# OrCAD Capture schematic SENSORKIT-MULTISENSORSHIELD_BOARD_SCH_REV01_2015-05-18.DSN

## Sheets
1 P01: RevisionHist: title: Sensor Platform Multi-Sensor Shield; rev: 01; note: Table of Contents/Revision History
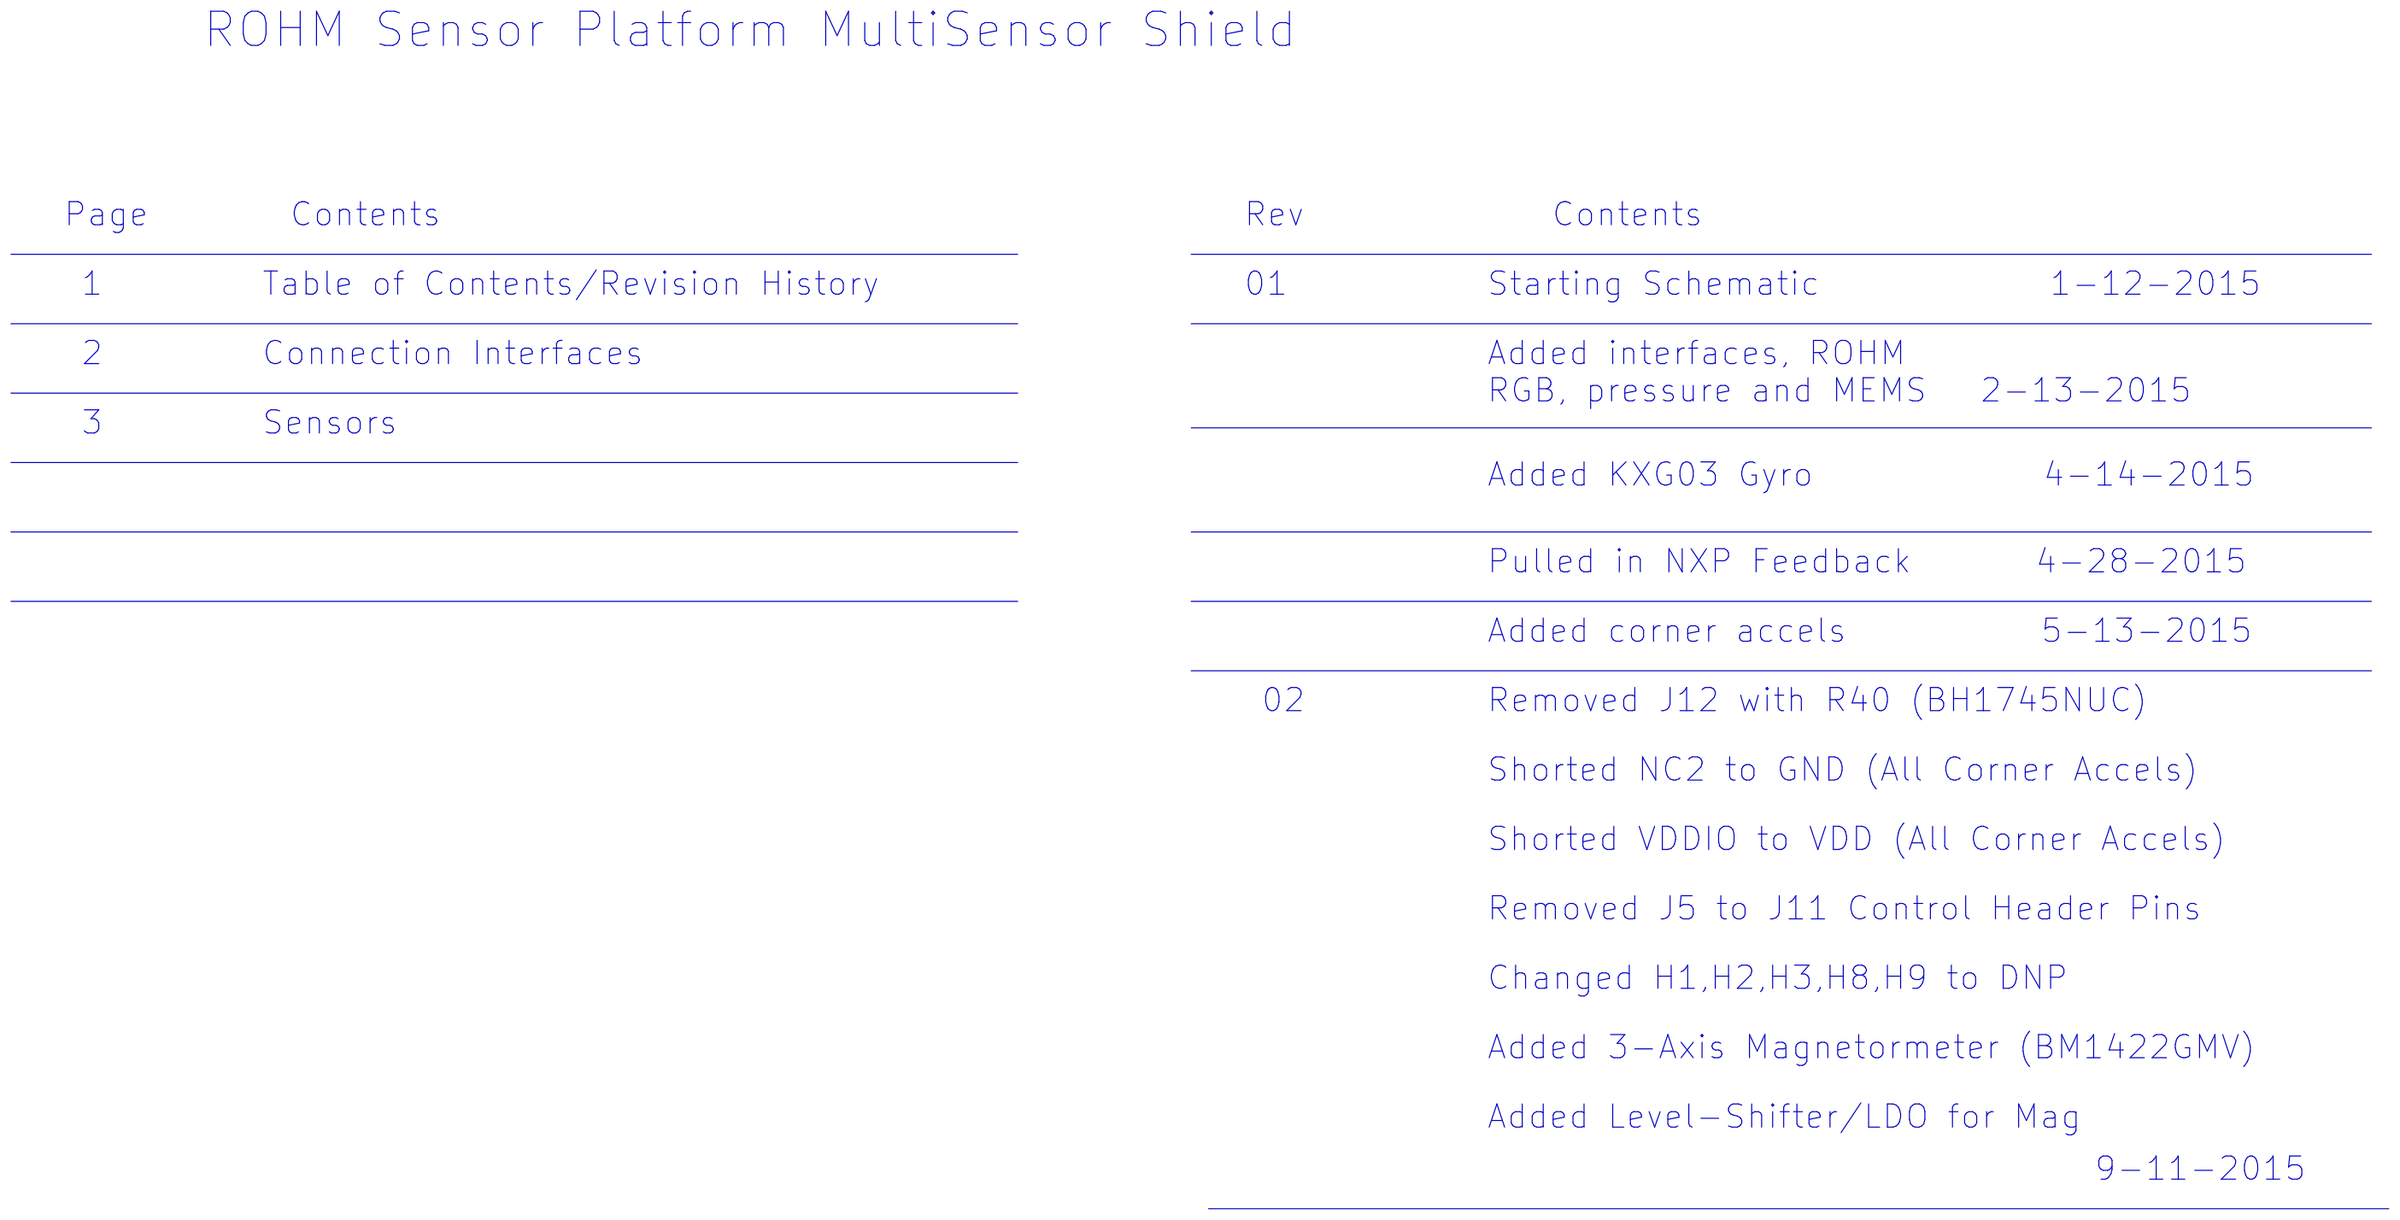
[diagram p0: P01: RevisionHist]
2 P03: Sensors: size C; note: Sensors
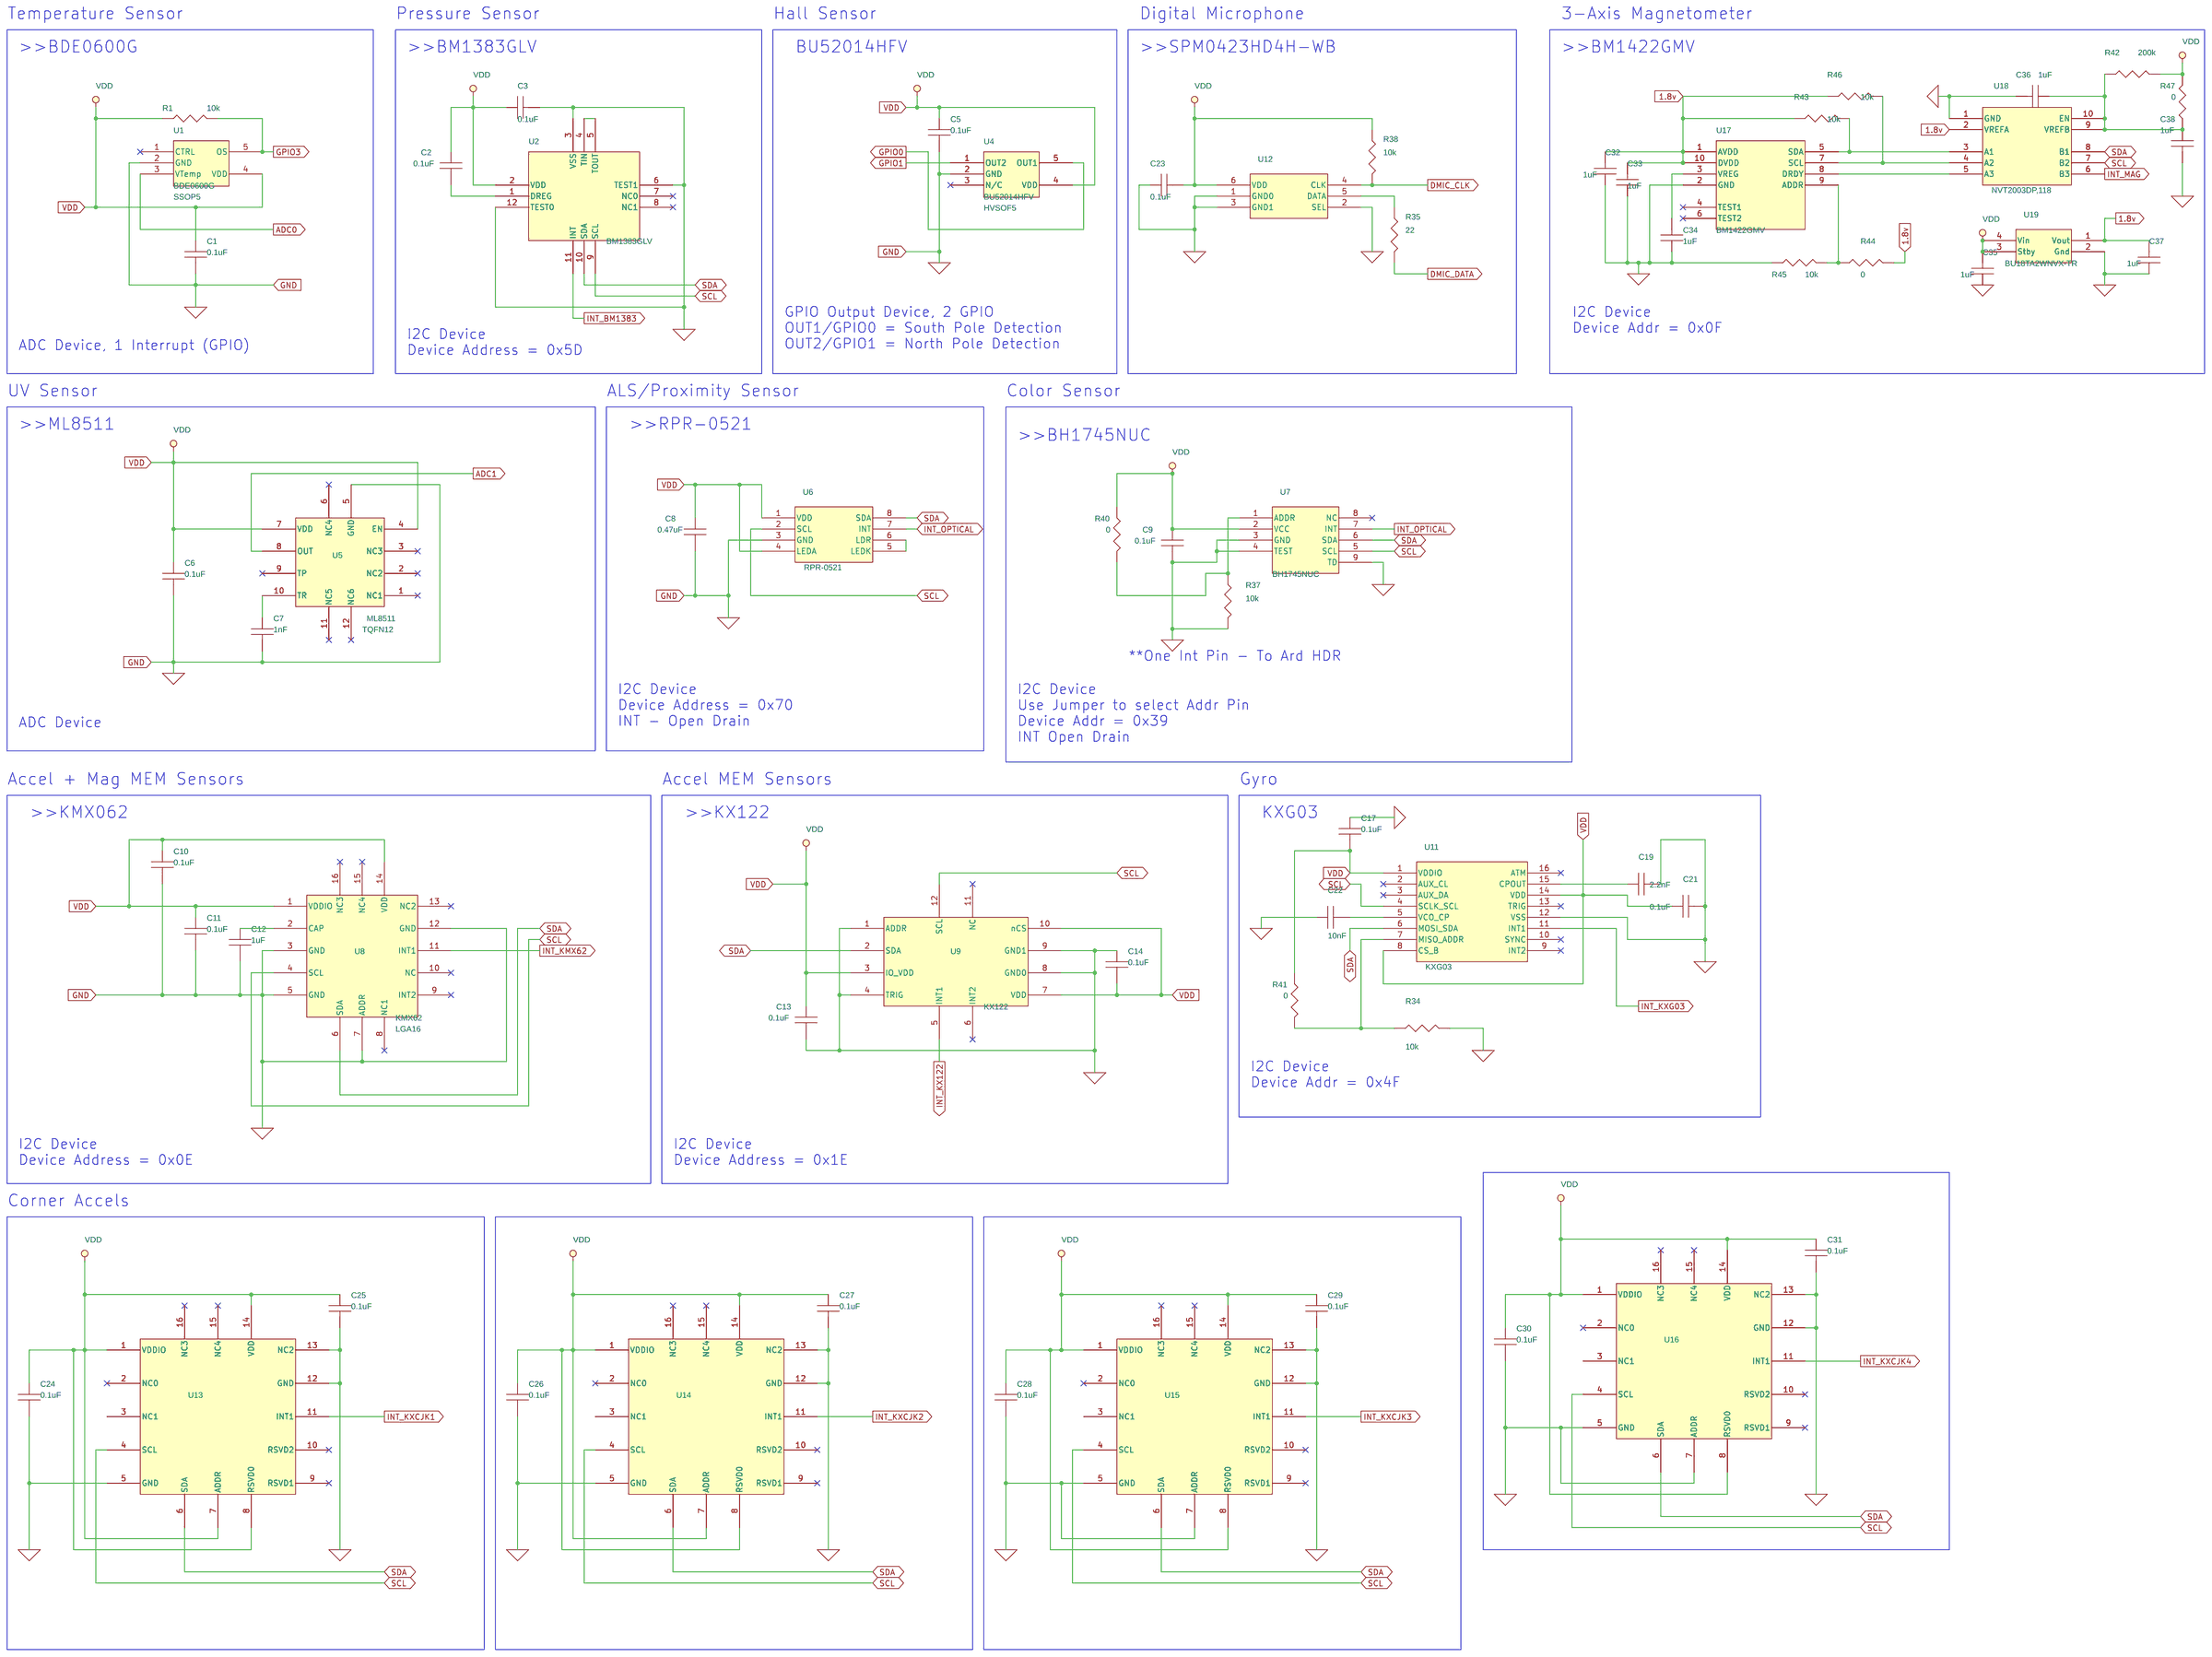
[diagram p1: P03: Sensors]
3 P02: Connection Interface: size B; note: Connection Interface
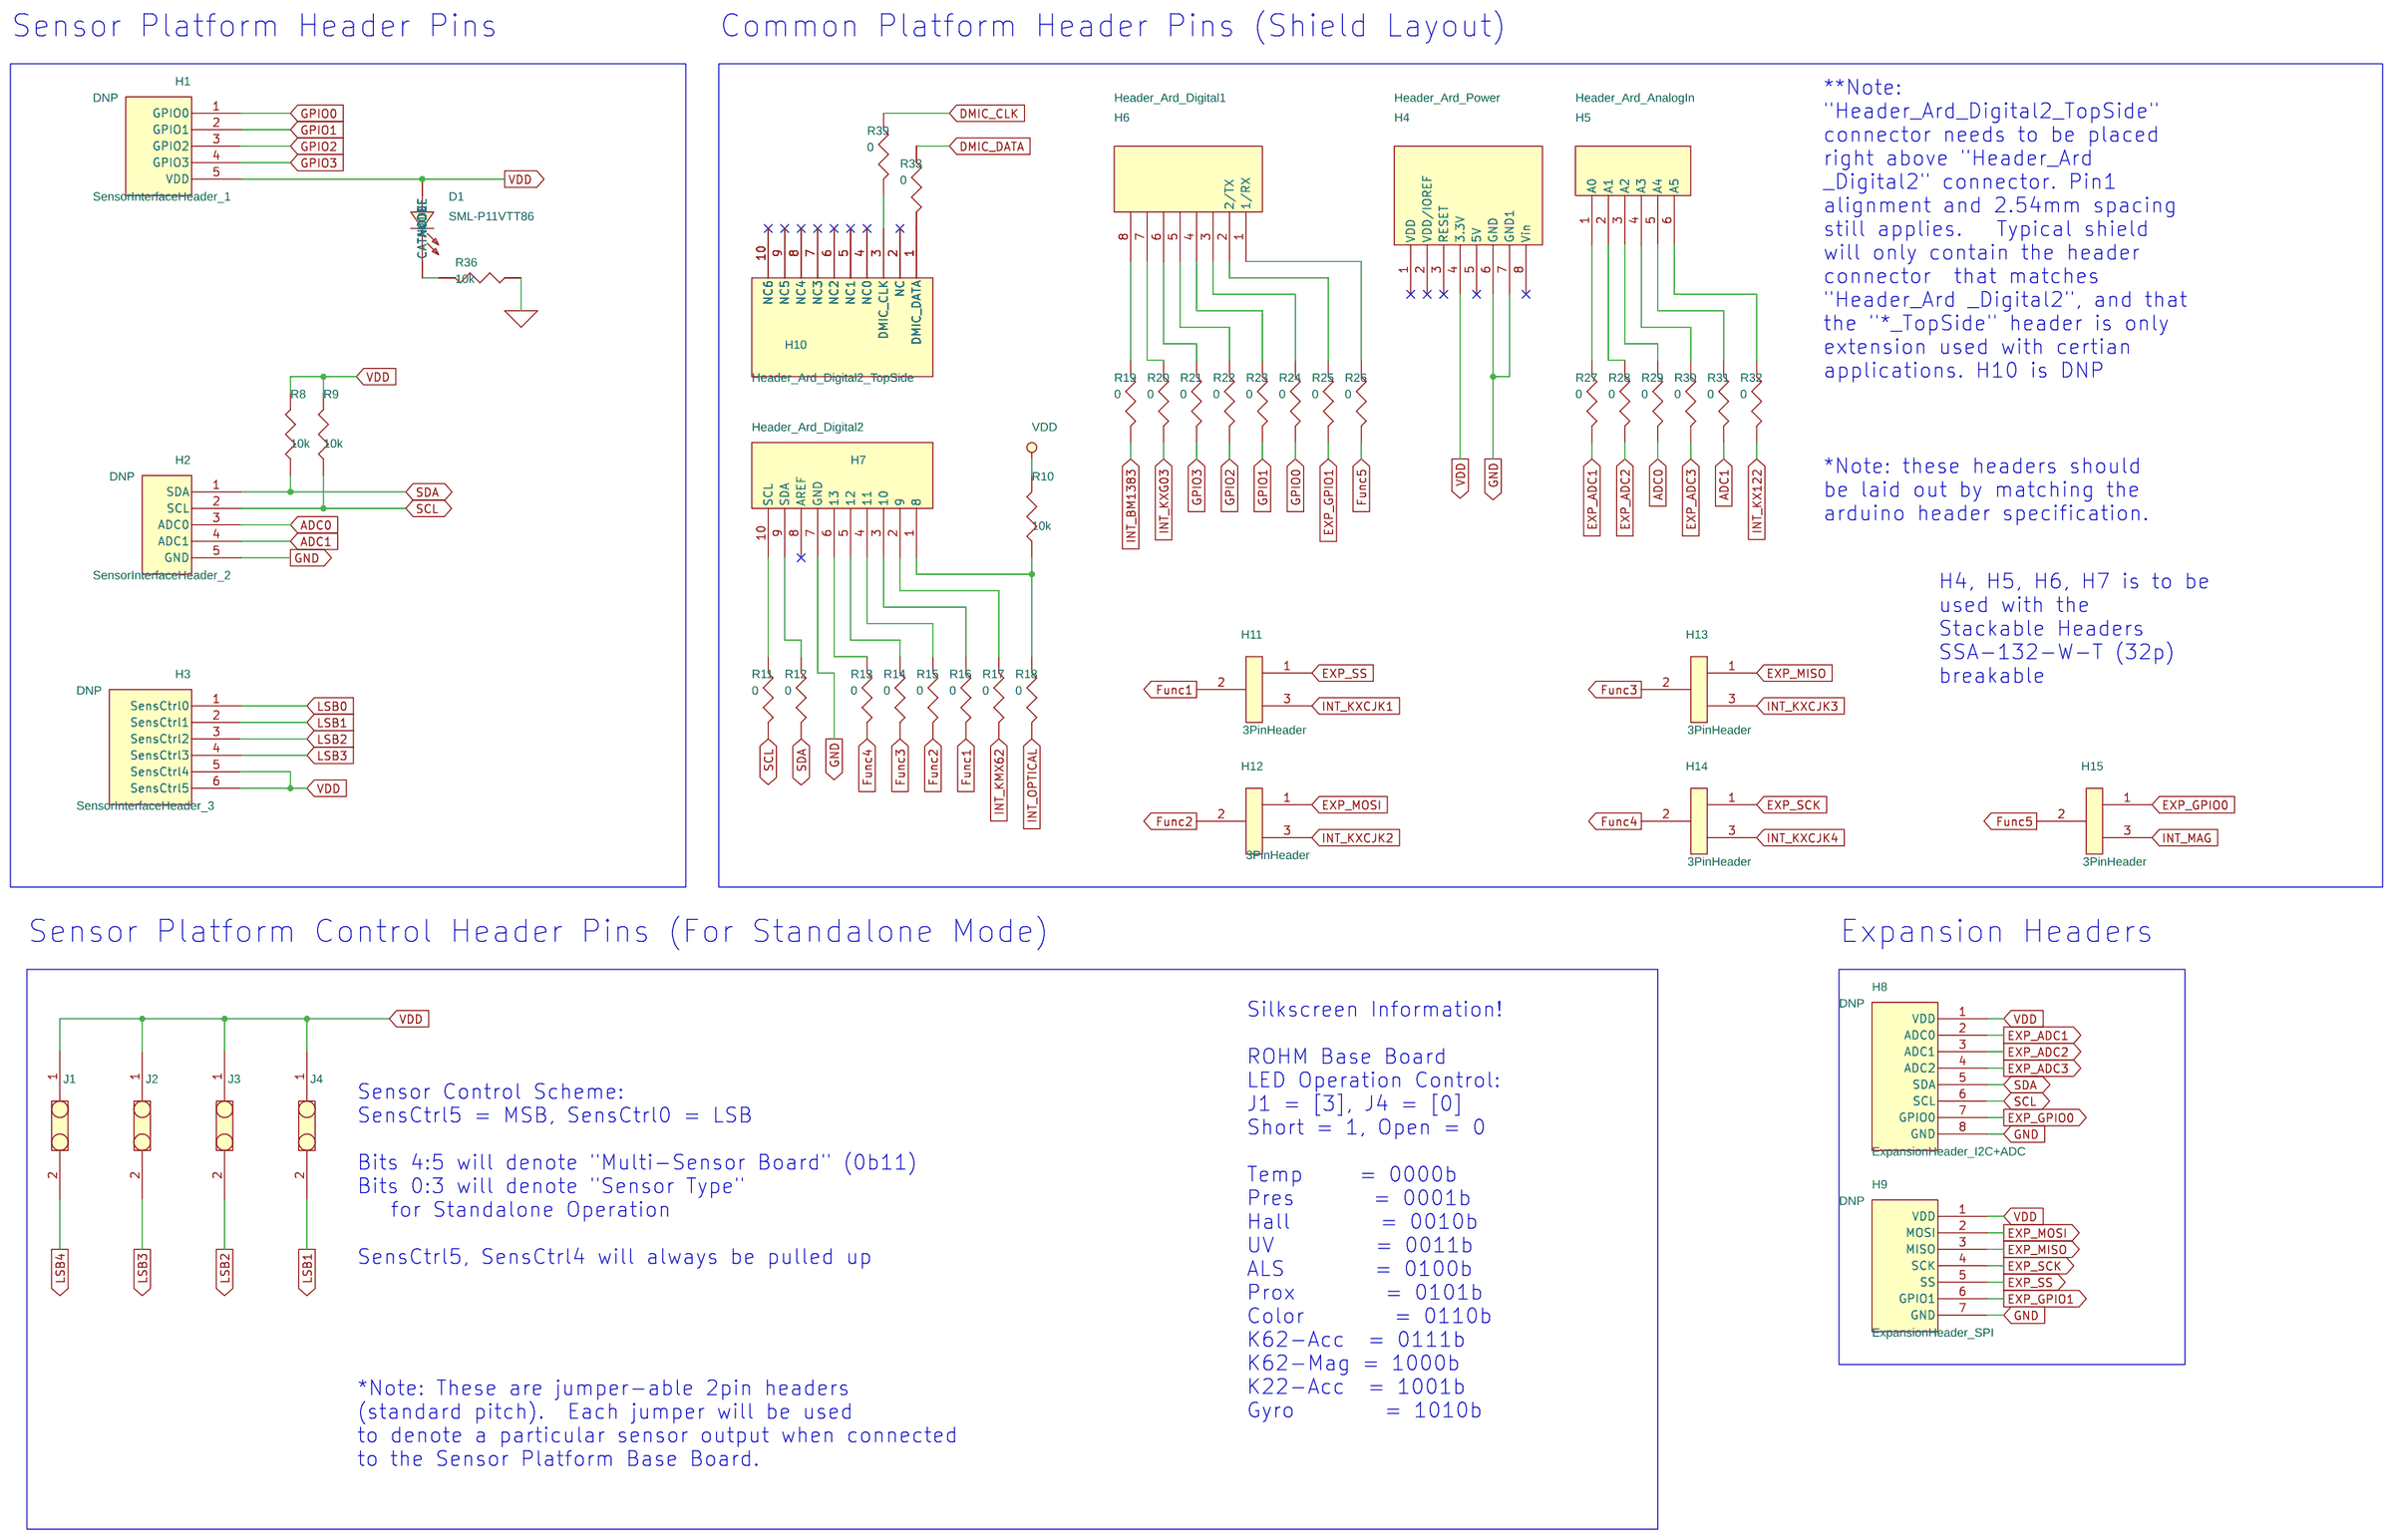
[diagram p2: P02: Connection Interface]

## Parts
sheet P02: Connection Interface
D1  SML-P11VTT86  [LED0402]
H1  SensorInterfaceHeader_1  [HDR_THVT_1X5_100]
H2  SensorInterfaceHeader_2  [HDR_THVT_1X5_100]
H3  SensorInterfaceHeader_3  [HDR_THVT_1X6_100]
H4  Header_Ard_Power  [HDR_THVT_1X8_100]
H5  Header_Ard_AnalogIn  [HDR_THVT_1X6_100]
H6  Header_Ard_Digital1  [HDR_THVT_1X8_100]
H7  Header_Ard_Digital2  [HDR_THVT_1X10_100]
H8  ExpansionHeader_I2C+ADC  [HDR_THVT_1X8_100]
H9  ExpansionHeader_SPI  [HDR_THVT_1X7_100]
H10  Header_Ard_Digital2_TopSide  [HDR_THVT_1X10_100]
H11  3PinHeader  [HDR_THVT_1X3_100]
H12  3PinHeader  [HDR_THVT_1X3_100]
H13  3PinHeader  [HDR_THVT_1X3_100]
H14  3PinHeader  [HDR_THVT_1X3_100]
H15  3PinHeader  [HDR_THVT_1X3_100]
J1  2-Pin Header  [HDR_THVT_1X2_100]
J2  2-Pin Header  [HDR_THVT_1X2_100]
J3  2-Pin Header  [HDR_THVT_1X2_100]
J4  2-Pin Header  [HDR_THVT_1X2_100]
R8  10k  [R0603]
R9  10k  [R0603]
R10  10k  [R0603]
R11  0  [R0603]
R12  0  [R0603]
R13  0  [R0603]
R14  0  [R0603]
R15  0  [R0603]
R16  0  [R0603]
R17  0  [R0603]
R18  0  [R0603]
R19  0  [R0603]
R20  0  [R0603]
R21  0  [R0603]
R22  0  [R0603]
R23  0  [R0603]
R24  0  [R0603]
R25  0  [R0603]
R26  0  [R0603]
R27  0  [R0603]
R28  0  [R0603]
R29  0  [R0603]
R30  0  [R0603]
R31  0  [R0603]
R32  0  [R0603]
R33  0  [R0603]
R36  10k  [R0603]
R39  0  [R0603]
sheet P03: Sensors
C1  0.1uF  [C0402]
C2  0.1uF  [C0402]
C3  0.1uF  [C0402]
C5  0.1uF  [C0402]
C6  0.1uF  [C0402]
C7  1nF  [C0402]
C8  0.47uF  [C0402]
C9  0.1uF  [C0402]
C10  0.1uF  [C0402]
C11  0.1uF  [C0402]
C12  1uF  [C0402]
C13  0.1uF  [C0402]
C14  0.1uF  [C0402]
C17  0.1uF  [C0402]
C19  2.2nF  [C0402]
C21  0.1uF  [C0402]
C22  10nF  [C0402]
C23  0.1uF  [C0402]
C24  0.1uF  [C0402]
C25  0.1uF  [C0402]
C26  0.1uF  [C0402]
C27  0.1uF  [C0402]
C28  0.1uF  [C0402]
C29  0.1uF  [C0402]
C30  0.1uF  [C0402]
C31  0.1uF  [C0402]
C32  1uF  [C0402]
C33  1uF  [C0402]
C34  1uF  [C0402]
C35  1uF  [C0402]
C36  1uF  [C0402]
C37  1uF  [C0402]
C38  1uF  [C0402]
R1  10k  [R0603]
R34  10k  [R0603]
R35  22  [R0603]
R37  10k  [R0603]
R38  10k  [R0603]
R40  0  [R0603]
R41  0  [R0603]
R42  200k  [R0603]
R43  10k  [R0603]
R44  0  [R0603]
R45  10k  [R0603]
R46  10k  [R0603]
R47  0  [R0603]
U1  BDE0600G  [SSOP5]
U2  BM1383GLV  [BM1383GLV]
U4  BU52014HFV  [HVSOF5]
U5  ML8511  [TQFN12]
U6  RPR-0521  [IC_3P94X2P36]
U7  BH1745NUC  [BH1745NUC]
U8  KMX62  [LGA_3x3x0P9]
U9  KX122  [LGA_2x2x0P9]
U11  KXG03  [LGA_3x3x0P9]
U12  SPM0423HD4H-WB  [IC_4P72X3P76]
U13  EVAL-KXCJK-1013  [LGA_3X3X0P9]
U14  EVAL-KXCJK-1013  [LGA_3X3X0P9]
U15  EVAL-KXCJK-1013  [LGA_3X3X0P9]
U16  EVAL-KXCJK-1013  [LGA_3X3X0P9]
U17  BM1422GMV  [MLLGA010V020A]
U18  NVT2003DP,118  [TSSOP10]
U19  BU18TA2WNVX-TR  [4SSON-EP]

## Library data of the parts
D1 = LED_0: LED 0402 RED 50MW 20MA SMD; DISTR1: ROHM; MFG1: ROHM; PACKAGE: 0403
H1 = SensorInterfaceHeader_1: CONN HEADER VERT SGL 5POS GOLD; DNP: DNP; Distr1: DIGIKEY; Distr1_part#: 3M9450-ND; Mfg1: 3M; Mfg1_part#: 961105-6404-AR
H2 = SensorInterfaceHeader_2: CONN HEADER VERT SGL 5POS GOLD; DNP: DNP; Distr1: DIGIKEY; Distr1_part#: 3M9450-ND; Mfg1: 3M; Mfg1_part#: 961105-6404-AR
H3 = SensorInterfaceHeader_3: CONN HEADER VERT SGL 6POS GOLD; DNP: DNP; Distr1: DIGIKEY; Distr1_part#: 3M9451-ND; Mfg1: 3M; Mfg1_part#: 961106-6404-AR
H4 = Header_Ard_Power_0
H5 = Header_Ard_AnalogIn
H6 = Header_Ard_Digital1_0
H7 = Header_Ard_Digital2
H8 = ExpansionHeader_I2C+ADC_0: DNP: DNP
H9 = ExpansionHeader_SPI_0: DNP: DNP
H10 = Header_Ard_Digital2_TopSide
H11-H15 = 3PinHeader
J1-J4 = 2-Pin_Header
R8-R10 = R: RES SMD 10K OHM 5% 1/10W 0603; BOM: EMPTY; Distr1: DIGIKEY; Distr1_part#: RHM10KCGTR-ND; Mfg1: Rohm Semiconductor; Mfg1_part#: MCR03ERTJ103; Package: 0603; Part Number: MCR03ERTJ103; Power: 0.1W, 1/10W; Tolerance: ±5%
R11-R33 R40 R41 R44 = R: RES 0.0 OHM 1/10W JUMP 0603 SMD; DISTR1: DIGIKEY; Distr1_part#: MCR03ERTJ000; MFG1: ROHM; Mfg1_part#: MCR03ERTJ000
R34 R36 R37 R45 = R: RES SMD 10K OHM 5% 1/10W 0603; BOM: EMPTY; Distr1: Digi-Key; Distr1_part#: RHM10KCGTR-ND; Mfg1: Rohm Semiconductor; Mfg1_part#: MCR03ERTJ103; Package: 0603; Part Number: MCR03ERTJ103; Power: 0.1W, 1/10W; Tolerance: ±5%
R39 = R: RES 0.0 OHM 1/10W JUMP 0603 SMD; DISTR1: DIGIKEY; Distr1_part#: MCR03ERTJ000; MFG1: ROHM; Mfg1_part#: MCR03ERTJ000; PACKAGE: 0603
C1-C3 C5 C6 C9-C11 C13 C14 C17 C21 C23-C38 = C_2: CAP CER 0.1UF 10V 10% X5R 0402; Distr1: DIGIKEY; Distr1_part#: 490-1318-1-ND; Mfg1: Murata; Mfg1_part#: GRM155R61A104KA01D; Package: 0402; STDCode: X5R; Tolerance: 10%; Voltage: 10V
C7 = C_2: CAP CER 1000PF 50V 10% X7R 0402; Distr1: DIGIKEY; Distr1_part#: 490-1303-1-ND; Mfg1: Murata; Mfg1_part#: GRM155R71H102KA01D; Package: 0402; STDCode: X7R; Tolerance: 10%; Voltage: 50V
C8 = C_2: CAP CER 0.47UF 10V 10% X5R 0402; Distr1: DIGIKEY; Distr1_part#: 490-3264-1-ND; Mfg1: Murata; Mfg1_part#: GRM155R61A474KE15D; Package: 0402; STDCode: X5R; Tolerance: 10%; Voltage: 10V
C12 = C_2: CAP CER 1UF 6.3V 10% X5R 0402; Distr1: DIGIKEY; Distr1_part#: 490-1320-1-ND; Mfg1: Murata; Mfg1_part#: GRM155R60J105KE19D; Package: 0402; STDCode: X5R; Tolerance: 10%; Voltage: 6.3V
C19 = C_2: CAP CER 2200PF 50V 5% X7R 0402; Distr1: DIGIKEY; Distr1_part#: 490-6359-1-ND; Mfg1: Murata; Mfg1_part#: GRM155R71H222JA01J; Package: 0402; STDCode: X5R; Tolerance: 10%; Voltage: 10V
C22 = C_2: CAP CER 10000PF 50V 10% X7R 0402; Distr1: DIGIKEY; Distr1_part#: 490-4516-1-ND; Mfg1: Murata; Mfg1_part#: GRM155R71H103KA88D; Package: 0402; STDCode: X5R; Tolerance: 10%; Voltage: 10V
R1 R38 R43 R46 = R: RES SMD 10K OHM 5% 1/10W 0603; BOM: EMPTY; Distr1: DIGIKEY; Distr1_part#: RHM10KCGTR-ND; Mfg1: Rohm; Mfg1_part#: MCR03ERTJ103; Package: 0603; Power: 1/10W; Tolerance: 5%
R35 R42 R47 = R: RES SMD 22 OHM 5% 1/10W 0603; BOM: EMPTY; Distr1: Digi-Key; Distr1_part#: RHM22CGTR-ND; Mfg1: Rohm Semiconductor; Mfg1_part#: MCR03ERTJ220; Package: 0603; Part Number: MCR03ERTJ220; Power: 0.1W, 1/10W; Tolerance: ±5%
U1 = HVSOF5_3: IC TEMP SENSOR THERM 60°C SSOP5; Distr1: DIGIKEY; Distr1_part#: BDE0600GCT-ND; Mfg1: Rohm; Mfg1_part#: BDE0600G-TR; Mfg2_part#: BDE0700G-TR; Mfg3_part#: BDE0800G-TR; Mfg4_part#: BDE0900G-TR; Mfg5_part#: BDE1000G-TR; Mfg6_part#: BDE1100G-TR
U2 = BM1383GLV: Pressure Sensor IC; DISTR1: ROHM; MFG1: ROHM
U4 = HVSOF5_1: IC HALL EFFECT SW BIPO HVSOF5; Distr1: DIGIKEY; Distr1_part#: BU52011HFV-TR; Mfg1: Rohm; Mfg1_part#: BU52011HFV-TR; Mfg2_part#: BU52012HFV-TR; Mfg3_part#: BU52013HFV-TR; Mfg4_part#: BU52014HFV-TR; Mfg5_part#: BU52021HFV-TR; Mfg6_part#: BU52040HFV
U5 = C-TQFN12-4.0x3.7-1_5.00: UV SENSOR W/AMP TQFN12; Distr1: DIGIKEY; Distr1_part#: ML8511-00FCZ05B; Mfg1: Rohm; Mfg1_part#: ML8511-00FCZ05B
U6 = RPR-0521_0: ALS/Proximity Sensor; DISTR1: Rohm; MFG1: Rohm
U7 = BH1745NUC_1: Color Sensor; DISTR1: Rohm; MFG1: Rohm
U8 = LGA_3.9: MAGNETOMETER AND ACCELEROMETER TRI-AXIS LGA16; Distr1: Kionix/Rohm; Mfg1: Kionix/Rohm; Package: LGA16
U9 = KX122: Accel MEM Sensors; DISTR1: Kionix/Rohm; MFG1: Kionix/Rohm
U11 = KXG03: Gyro Sensor; DISTR1: Kionix/Rohm; MFG1: Kionix/Rohm
U12 = SPM0423HD4H-WB: MIC MEMS DIGITAL PDM OMNI -26DB; DISTR1: Digi-Key; DISTR1_PART#: 423-1126-2-ND; MFG1: Knowles; Package: 4P72X3P76
U13-U16 = KXCJK: BOARD EVAL KXCJK ACCELEROMETER; DISTR1: Digi-Key; DISTR1_PART#: EVAL-KXCJK-1013-ND; MFG1: Kionix Inc; Package: 3X3X0P9
U17 = BM1422GMV
U18 = NVT2003DP,118
U19 = BU18TA2WNVX-TR

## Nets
1.8v: C32.2 C33.2 C37.2 R43.1 R44.2 R46.1 U17.1(AVDD) U17.10(DVDD) U18.2(VREFA) U19.1(Vout)
GND_HL2_2: C1.2 C3.2 C5.2 C6.2 C7.2 C8.2 C9.2 C10.2 C11.2 C12.2 C13.2 C14.1 C17.1 C19.2 C21.2 C22.1 C23.1 C24.2 C25.2 C26.2 C27.2 C28.2 C29.2 C30.2 C31.2 C32.1 C33.1 C34.1 C35.1 C36.2 C37.1 C38.2 H2.5(GND) H4.6(GND) H4.7(GND1) H7.7(GND) H8.8(GND) H9.7(GND) R34.2 R36.1 R37.2 R45.1 U1.2(GND) U2.3(VSS) U2.6(TEST1) U2.12(TEST0) U4.2(GND) U5.5(GND) U6.3(GND) U7.3(GND) U7.4(TEST) U7.9(TD) U8.3(GND) U8.5(GND) U8.7(ADDR) U8.12(GND) U9.1(ADDR) U9.4(TRIG) U9.8(GND0) U9.9(GND1) U11.12(VSS) U12.1(GND0) U12.2(SEL) U12.3(GND1) U13.5(GND) U13.12(GND) U13.13(NC2) U14.5(GND) U14.12(GND) U14.13(NC2) U15.5(GND) U15.7(ADDR) U15.12(GND) U15.13(NC2) U16.5(GND) U16.7(ADDR) U16.12(GND) U16.13(NC2) U17.2(GND) U18.1(GND) U19.2(Gnd)
VDD: C1.1 C2.1 C3.1 C5.1 C6.1 C8.1 C9.1 C10.1 C11.1 C13.1 C14.2 C17.2 C21.1 C23.2 C24.1 C25.1 C26.1 C27.1 C28.1 C29.1 C30.1 C31.1 C35.2 D1.A(ANODE) H1.5(VDD) H3.5(SensCtrl4) H3.6(SensCtrl5) H4.4(3.3V) H8.1(VDD) H9.1(VDD) J1.1 J2.1 J3.1 J4.1 R1.1 R8.2 R9.2 R10.2 R38.1 R40.1 R41.1 R42.2 R47.2 U1.4(VDD) U2.2(VDD) U4.4(VDD) U5.4(EN) U5.7(VDD) U6.1(VDD) U6.4(LEDA) U7.2(VCC) U8.1(VDDIO) U8.14(VDD) U9.3(IO_VDD) U9.7(VDD) U9.10(nCS) U11.1(VDDIO) U11.8(CS_B) U11.14(VDD) U12.6(VDD) U13.1(VDDIO) U13.7(ADDR) U13.8(RSVD0) U13.14(VDD) U14.1(VDDIO) U14.7(ADDR) U14.8(RSVD0) U14.14(VDD) U15.1(VDDIO) U15.8(RSVD0) U15.14(VDD) U16.1(VDDIO) U16.8(RSVD0) U16.14(VDD) U19.3(Stby) U19.4(Vin)
ADC0: H2.3(ADC0) R29.2 U1.3(VTemp)
ADC1: H2.4(ADC1) R31.2 U5.8(OUT)
DMIC_CLK: R38.2 R39.1 U12.4(CLK)
DMIC_DATA: R33.1 R35.2
EXP_ADC1: H8.2(ADC0) R27.2
EXP_ADC2: H8.3(ADC1) R28.2
EXP_ADC3: H8.4(ADC2) R30.2
EXP_GPIO0: H8.7(GPIO0) H15.1
EXP_GPIO1: H9.6(GPIO1) R25.2
EXP_MISO: H9.3(MISO) H13.1
EXP_MOSI: H9.2(MOSI) H12.1
EXP_SCK: H9.4(SCK) H14.1
EXP_SS: H9.5(SS) H11.1
Func1: H11.2 R16.2
Func2: H12.2 R15.2
Func3: H13.2 R14.2
Func4: H14.2 R13.2
Func5: H15.2 R26.2
GPIO0: H1.1(GPIO0) R24.2 U4.5(OUT1)
GPIO1: H1.2(GPIO1) R23.2 U4.1(OUT2)
GPIO2: H1.3(GPIO2) R22.2
GPIO3: H1.4(GPIO3) R1.2 R21.2 U1.5(OS)
INT_BM1383: R19.2 U2.11(INT)
INT_KMX62: R17.2 U8.11(INT1)
INT_KX122: R32.2 U9.5(INT1)
INT_KXCJK1: H11.3 U13.11(INT1)
INT_KXCJK2: H12.3 U14.11(INT1)
INT_KXCJK3: H13.3 U15.11(INT1)
INT_KXCJK4: H14.3 U16.11(INT1)
INT_KXG03: R20.2 U11.11(INT1)
INT_MAG: H15.3 U18.6(B3)
INT_OPTICAL: R18.2 U6.7(INT) U7.7(INT)
LSB0: H3.1(SensCtrl0)
LSB1: H3.2(SensCtrl1) J4.2
LSB2: H3.3(SensCtrl2) J3.2
LSB3: H3.4(SensCtrl3) J2.2
LSB4: J1.2
NC1: U13.3(NC1) U14.3(NC1) U15.3(NC1) U16.3(NC1)
SCL: H2.2(SCL) H8.6(SCL) R9.1 R11.2 U2.9(SCL) U6.2(SCL) U7.5(SCL) U8.4(SCL) U9.12(SCL) U11.4(SCLK_SCL) U13.4(SCL) U14.4(SCL) U15.4(SCL) U16.4(SCL) U18.7(B2)
SDA: H2.1(SDA) H8.5(SDA) R8.1 R12.2 U2.10(SDA) U6.8(SDA) U7.6(SDA) U8.6(SDA) U9.2(SDA) U11.6(MOSI_SDA) U13.6(SDA) U14.6(SDA) U15.6(SDA) U16.6(SDA) U18.8(B1)
N14002690: C12.1 U8.2(CAP)
N14009218: C7.1 U5.10(TR)
N14013380: U6.5(LEDK) U6.6(LDR)
N14046481: R37.1 R40.2 U7.1(ADDR)
N14046877: U2.4(TIN) U2.5(TOUT)
N14048054: C2.2 U2.1(DREG)
N14096363: D1.C(CATHODE) R36.2
N14097558: H7.10(SCL) R11.1
N14097562: H7.9(SDA) R12.1
N14097578: H7.5(12) R14.1
N14097590: H7.4(11) R15.1
N14097622: H7.3(10) R16.1
N14097634: H7.2(9) R17.1
N14097646: H7.1(8) R10.1 R18.1
N14098075: H6.8 R19.1
N14098079: H6.7 R20.1
N14098086: H6.6 R21.1
N14098098: H6.5 R22.1
N14098110: H6.4 R23.1
N14098122: H6.3 R24.1
N14098134: H6.2(2/TX) R25.1
N14098146: H6.1(1/RX) R26.1
N14098493: H5.1(A0) R27.1
N14098497: H5.2(A1) R28.1
N14098504: H5.3(A2) R29.1
N14098516: H5.4(A3) R30.1
N14098528: H5.5(A4) R31.1
N14098540: H5.6(A5) R32.1
N14105342: C19.1 U11.15(CPOUT)
N14105886: C22.2 U11.5(VCO_CP)
N14107068: R34.1 R41.2 U11.7(MISO_ADDR)
N14121723: H7.6(13) R13.1
N14122965: H10.3(DMIC_CLK) R39.2
N14126545: R35.1 U12.5(DATA)
N14187344: H10.1(DMIC_DATA) R33.2
N14207646: C34.2 U17.3(VREG)
N14208918: R46.2 U17.7(SCL) U18.4(A2)
N14209514: U17.8(DRDY) U18.5(A3)
N14210198: R44.1 R45.2 U17.9(ADDR)
N14210289: R43.2 U17.5(SDA) U18.3(A1)
N14216212: C36.1 C38.1 R42.1 R47.1 U18.9(VREFB) U18.10(EN)

Not connected (* = marked no-connect by the designer): H4 1(VDD)* 2(VDD/IOREF)* 3(RESET)* 5(5V)* 8(Vin)*; H7 8(AREF)*; H10 2(NC)* 4(NC0)* 5(NC1)* 6(NC2)* 7(NC3)* 8(NC4)* 9(NC5)* 10(NC6)*; U1 1(CTRL)*; U2 7(NC0)* 8(NC1)*; U4 3(N/C)*; U5 1(NC1)* 2(NC2)* 3(NC3)* 6(NC4)* 9(TP)* 11(NC5)* 12(NC6)*; U7 8(NC)*; U8 8(NC1)* 9(INT2)* 10(NC)* 13(NC2)* 15(NC4)* 16(NC3)*; U9 6(INT2)* 11(NC)*; U11 2(AUX_CL)* 3(AUX_DA)* 9(INT2)* 10(SYNC)* 13(TRIG)* 16(ATM)*; U13 2(NC0)* 9(RSVD1)* 10(RSVD2)* 15(NC4)* 16(NC3)*; U14 2(NC0)* 9(RSVD1)* 10(RSVD2)* 15(NC4)* 16(NC3)*; U15 2(NC0)* 9(RSVD1)* 10(RSVD2)* 15(NC4)* 16(NC3)*; U16 2(NC0)* 9(RSVD1)* 10(RSVD2)* 15(NC4)* 16(NC3)*; U17 4(TEST1)* 6(TEST2)*

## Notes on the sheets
sheet 1
- ROHM Sensor Platform MultiSensor Shield
- Page        Contents
- Rev              Contents
- 1         Table of Contents/Revision History
- 01
- Starting Schematic             1-12-2015
- 2         Connection Interfaces
- Added interfaces, ROHM
  RGB, pressure and MEMS   2-13-2015
- 3         Sensors
- Added KXG03 Gyro             4-14-2015
- Pulled in NXP Feedback       4-28-2015
- Added corner accels           5-13-2015
- 02
- Removed J12 with R40 (BH1745NUC)
- Shorted NC2 to GND (All Corner Accels)
- Shorted VDDIO to VDD (All Corner Accels)
- Removed J5 to J11 Control Header Pins
- Changed H1,H2,H3,H8,H9 to DNP
- Added 3-Axis Magnetormeter (BM1422GMV)
- Added Level-Shifter/LDO for Mag
- 9-11-2015
sheet 2
- Temperature Sensor
- Pressure Sensor
- Hall Sensor
- Digital Microphone
- 3-Axis Magnetometer
- >>BDE0600G
- >>BM1383GLV
- BU52014HFV
- >>SPM0423HD4H-WB
- >>BM1422GMV
- GPIO Output Device, 2 GPIO
  OUT1/GPIO0 = South Pole Detection
  OUT2/GPIO1 = North Pole Detection
- I2C Device
  Device Addr = 0x0F
- ADC Device, 1 Interrupt (GPIO)
- I2C Device
  Device Address = 0x5D
- UV Sensor
- ALS/Proximity Sensor
- Color Sensor
- >>ML8511
- >>RPR-0521
- >>BH1745NUC
- **One Int Pin - To Ard HDR
- I2C Device
  Device Address = 0x70
  INT - Open Drain
- I2C Device
  Use Jumper to select Addr Pin
  Device Addr = 0x39
  INT Open Drain
- ADC Device
- Accel + Mag MEM Sensors
- Accel MEM Sensors
- Gyro
- >>KMX062
- >>KX122
- KXG03
- I2C Device
  Device Addr = 0x4F
- I2C Device
  Device Address = 0x0E
- I2C Device
  Device Address = 0x1E
- Corner Accels
sheet 3
- Sensor Platform Header Pins
- Common Platform Header Pins (Shield Layout)
- **Note:
  "Header_Ard_Digital2_TopSide"
  connector needs to be placed
  right above "Header_Ard
  _Digital2" connector. Pin1
  alignment and 2.54mm spacing
  still applies.   Typical shield
  will only contain the header
  connector  that matches
  "Header_Ard _Digital2", and that
  the "*_TopSide" header is only
  extension used with certian
  applications. H10 is DNP
- *Note: these headers should
  be laid out by matching the
  arduino header specification.
- H4, H5, H6, H7 is to be
  used with the
  Stackable Headers
  SSA-132-W-T (32p)
  breakable
- Sensor Platform Control Header Pins (For Standalone Mode)
- Expansion Headers
- Silkscreen Information!
  ROHM Base Board
  LED Operation Control:
  J1 = [3], J4 = [0]
  Short = 1, Open = 0
  Temp     = 0000b
  Pres       = 0001b
  Hall        = 0010b
  UV         = 0011b
  ALS        = 0100b
  Prox        = 0101b
  Color        = 0110b
  K62-Acc  = 0111b
  K62-Mag = 1000b
  K22-Acc  = 1001b
  Gyro        = 1010b
- Sensor Control Scheme:
  SensCtrl5 = MSB, SensCtrl0 = LSB
  Bits 4:5 will denote "Multi-Sensor Board" (0b11)
  Bits 0:3 will denote "Sensor Type"
     for Standalone Operation
  SensCtrl5, SensCtrl4 will always be pulled up
- *Note: These are jumper-able 2pin headers
  (standard pitch).  Each jumper will be used
  to denote a particular sensor output when connected
  to the Sensor Platform Base Board.
